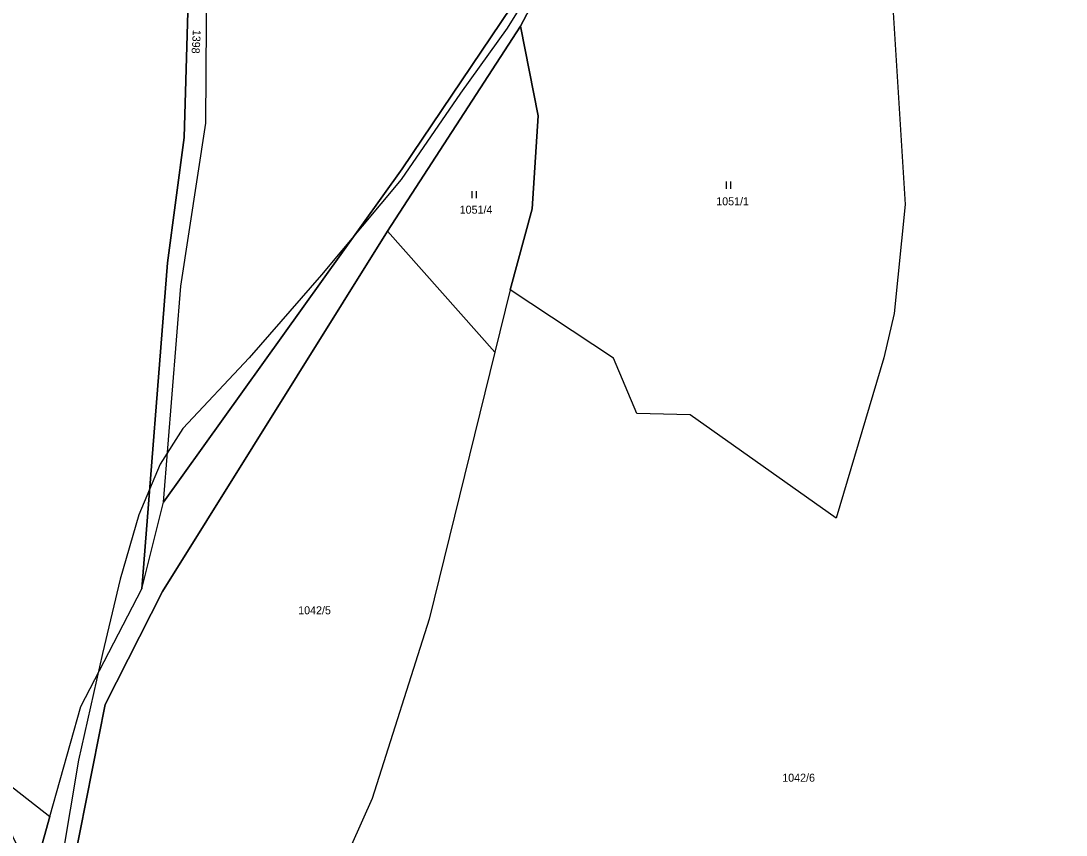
# Model space of a CAD drawing. Extents: x -588699 to -585793, y -1060280 to -1056731.
# Drawn here: x -588042.9 to -587820.9, y -1058596 to -1058423.1 of the extents above; entities that cross this region are included whole.
import ezdxf

# ---------------------------------------------------------------- set-up
doc = ezdxf.new("R2010")
doc.units = 0
for name, color, linetype in [('Druh pozemku', 7, 'Continuous'), ('Parcela nároku', 7, 'Continuous'), ('Vnitřní obvod', 7, 'Continuous')]:
    doc.layers.add(name, color=color, linetype=linetype)

msp = doc.modelspace()

# ---------------------------------------------------------------- linework, layer by layer
at = {"layer": 'Druh pozemku'}
for p, q in [((-587893.17, -1058457.25), (-587893.17, -1058458.75)), ((-587892.15, -1058458.75), (-587892.15, -1058457.25)), ((-587947.17, -1058459.29), (-587947.17, -1058460.79)), ((-587946.15, -1058460.79), (-587946.15, -1058459.29))]:
    msp.add_line(p, q, dxfattribs=at)
at = {"layer": 'Parcela nároku'}
for points in [[(-588040.36, -1058604.95), (-588036.79, -1058592.04), (-588030.19, -1058568.64), (-588017.25, -1058543.67), (-588012.66, -1058525.33), (-587961.97, -1058454.52), (-587938.78, -1058420.23), (-587909.15, -1058354.04), (-587902.69, -1058339.62), (-587893.69, -1058331.59), (-587887.79, -1058328.34), (-587882.85, -1058325.77), (-587861.42, -1058325.37), (-587847.92, -1058320.82), (-587830.54, -1058313.79), (-587820.75, -1058311.88)], [(-587802.9, -1058312.42), (-587827.99, -1058317.83), (-587843.58, -1058322.89), (-587847.11, -1058324.03), (-587861.97, -1058328.85), (-587878.04, -1058329.7), (-587880.58, -1058329.83), (-587891.44, -1058332.71), (-587901.12, -1058343.38), (-587920.13, -1058389.62), (-587922.13, -1058394.48), (-587934.83, -1058420.52), (-587936.82, -1058424.26), (-587965.05, -1058467.76), (-588012.84, -1058544.25), (-588025, -1058568.22), (-588031.77, -1058602.2)], [(-587802.9, -1058312.42), (-587827.99, -1058317.83), (-587843.58, -1058322.89), (-587841.94, -1058345.38), (-587833.09, -1058345.02), (-587821.05, -1058404.07), (-587824.28, -1058406.66), (-587834.67, -1058403.29), (-587857.73, -1058420.24), (-587855.1, -1058462.1), (-587857.43, -1058485.22), (-587859.67, -1058494.65), (-587869.76, -1058528.68), (-587900.79, -1058506.76), (-587912.08, -1058506.47), (-587917.05, -1058494.72), (-587939.01, -1058480.19), (-587942.29, -1058493.44), (-587956.18, -1058550.14), (-587968.29, -1058588.22), (-587991.4, -1058639.93)]]:
    msp.add_lwpolyline(points, dxfattribs=at)
for points in [[(-588009.33, -1058355.16), (-587995.38, -1058336.3), (-587964.13, -1058321.19), (-587958.92, -1058331.64), (-587954.45, -1058349.62), (-587944.97, -1058387.78), (-587938.78, -1058420.23), (-587961.97, -1058454.52), (-588012.66, -1058525.33), (-588008.92, -1058479.42), (-588003.61, -1058444.87), (-588003.45, -1058412.71), (-588013.49, -1058358.01)], [(-588007.26, -1058413.92), (-588008.24, -1058447.9), (-588011.81, -1058474.47), (-588017.25, -1058543.67), (-588012.66, -1058525.33), (-588008.92, -1058479.42), (-588003.61, -1058444.87), (-588003.45, -1058412.71), (-588013.49, -1058358.01), (-588016.09, -1058359.8), (-588011.34, -1058388.91)], [(-588096.98, -1058493.24), (-588105.09, -1058523.12), (-588108.4, -1058531.35), (-588109.84, -1058534.93), (-588036.79, -1058592.04), (-588030.19, -1058568.64), (-588017.25, -1058543.67), (-588011.81, -1058474.47), (-588008.24, -1058447.9), (-588007.26, -1058413.92), (-588019.83, -1058414.9), (-588024.83, -1058386.7), (-588025.09, -1058385.21), (-588049.02, -1058399.97), (-588096, -1058425.03), (-588091.36, -1058450.44)], [(-587936.82, -1058424.26), (-587934.83, -1058420.52), (-587922.13, -1058394.48), (-587920.13, -1058389.62), (-587863.69, -1058415.11), (-587864.47, -1058420.24), (-587857.73, -1058420.24), (-587855.1, -1058462.1), (-587857.43, -1058485.22), (-587859.67, -1058494.65), (-587869.76, -1058528.68), (-587900.79, -1058506.76), (-587912.08, -1058506.47), (-587917.05, -1058494.72), (-587939.01, -1058480.19), (-587934.31, -1058463.01), (-587933.04, -1058443.26)], [(-587965.05, -1058467.76), (-587936.82, -1058424.26), (-587933.04, -1058443.26), (-587934.31, -1058463.01), (-587939.01, -1058480.19), (-587942.29, -1058493.44)], [(-588012.84, -1058544.25), (-587965.05, -1058467.76), (-587942.29, -1058493.44), (-587956.18, -1058550.14), (-587968.29, -1058588.22), (-587991.4, -1058639.93), (-588003.03, -1058661.2), (-588031.77, -1058602.2), (-588025, -1058568.22)], [(-588109.84, -1058534.93), (-588036.79, -1058592.04), (-588040.36, -1058604.95), (-588044.66, -1058596.24), (-588112.84, -1058542.38)]]:
    msp.add_lwpolyline(points, close=True, dxfattribs=at)
at = {"layer": 'Vnitřní obvod'}
msp.add_lwpolyline([(-587879.9, -1058327.72), (-587885.77, -1058328.52), (-587892.95, -1058331.81), (-587901.05, -1058339.29), (-587904.22, -1058344.92), (-587911.87, -1058361.33), (-587918.81, -1058377.04), (-587923.86, -1058391.35), (-587928.25, -1058403.78), (-587932.71, -1058413.52), (-587939.62, -1058424.69), (-587949.54, -1058438.46), (-587962.19, -1058456.81), (-587979.07, -1058477.07), (-587994.46, -1058494.67), (-588008.55, -1058509.64), (-588013.35, -1058517.24), (-588017.9, -1058527.99), (-588021.8, -1058541.63), (-588025.58, -1058557.42), (-588030.66, -1058580.1), (-588034.23, -1058601.15)], dxfattribs=at)

# ---------------------------------------------------------------- texts
at = {"layer": 'Parcela nároku'}
msp.add_text('1398', height=1.7, rotation=266.6422, dxfattribs=at).set_placement((-588006.38, -1058424.98))
for s, p in [('1051/4', (-587949.73, -1058464.06)), ('1051/1', (-587895.25, -1058462.28)), ('1042/5', (-587984.03, -1058549.1)), ('1042/6', (-587881.23, -1058584.64))]:
    msp.add_text(s, height=1.7, dxfattribs=at).set_placement(p)

doc.saveas('drawing.dxf')
